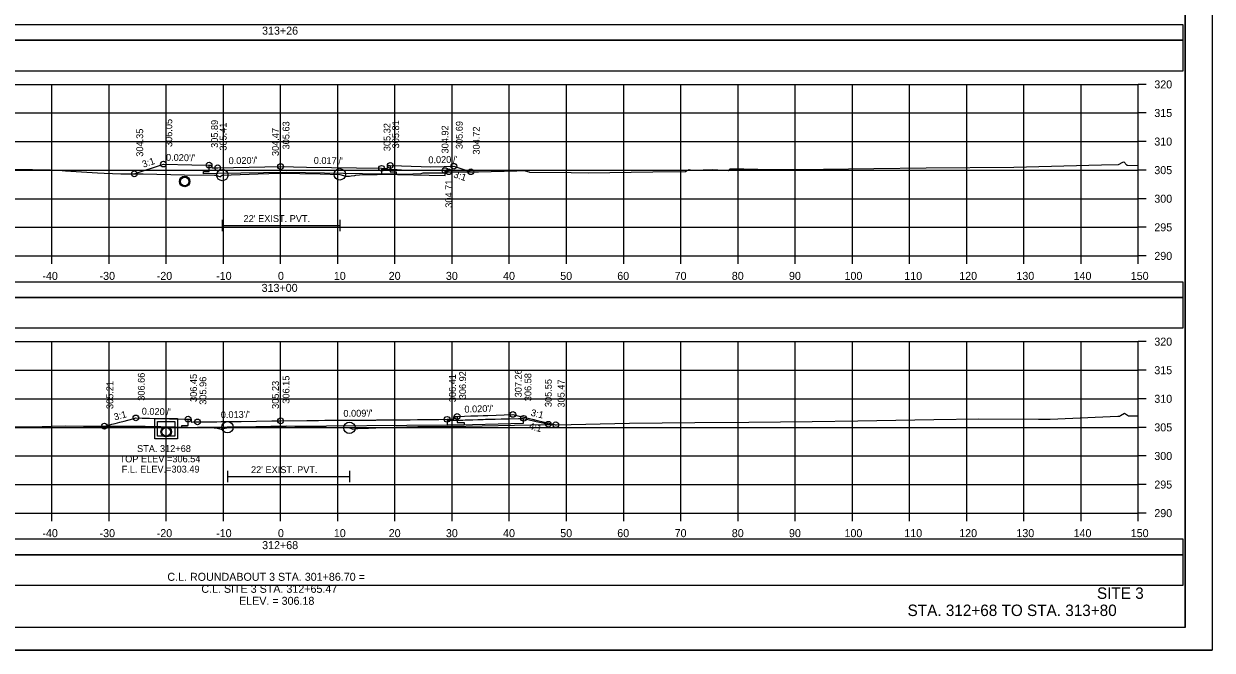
# Model space of a CAD drawing. Extents: x 1370538 to 1372872, y 376220 to 381127.
# Drawn here: x 1371330.4 to 1371538.2, y 378049.2 to 378158.8 of the extents above; entities that cross this region are included whole.
import ezdxf

# ---------------------------------------------------------------- set-up
doc = ezdxf.new("R2010")
doc.units = 0
for name, color, linetype in [('R_Border', 7, 'Continuous'), ('R_Border Notes', 7, 'Continuous'), ('R_Border PE', 7, 'Continuous'), ('R_Border Prem', 7, 'Continuous'), ('R_Dimension', 7, 'Continuous'), ('R_Fin Surface', 7, 'Continuous'), ('R_Grid', 7, 'Continuous'), ('R_Horz Alg Annot', 7, 'Continuous'), ('R_No Plot', 7, 'Continuous'), ('R_Proposed Road', 7, 'Continuous'), ('R_Water', 7, 'Continuous'), ('R_Water Annot', 7, 'Continuous'), ('R_Xsect Elev', 7, 'Continuous'), ('R_Xsect Slope', 7, 'Continuous')]:
    doc.layers.add(name, color=color, linetype=linetype)

msp = doc.modelspace()

# ---------------------------------------------------------------- linework, layer by layer
at = {"layer": 'R_Border'}
for p, q in [((1371365.1, 378124.52), (1371365.1, 378122.52)), ((1371385.64, 378124.52), (1371385.64, 378122.52)), ((1371365.1, 378123.52), (1371385.64, 378123.52)), ((1371366, 378080.59), (1371366, 378078.59)), ((1371366, 378079.59), (1371387.33, 378079.59)), ((1371387.33, 378080.59), (1371387.33, 378078.59))]:
    msp.add_line(p, q, dxfattribs=at)
for points in [[(1371376.35, 378132.79), (1371364.29, 378132.6), (1371361.79, 378132.55), (1371361.79, 378132.96), (1371362.79, 378132.98), (1371362.79, 378134.08)], [(1371394.47, 378134), (1371394.47, 378132.9), (1371395.48, 378132.89), (1371395.48, 378132.47), (1371392.96, 378132.51), (1371376.35, 378132.79)], [(1371376.27, 378088.34), (1371360.76, 378088.15), (1371358, 378088.11), (1371358, 378088.53), (1371359.11, 378088.54), (1371359.11, 378089.64)], [(1371406.18, 378090.11), (1371406.18, 378089.02), (1371407.37, 378089.02), (1371407.37, 378088.6), (1371404.4, 378088.6), (1371376.27, 378088.34)]]:
    msp.add_lwpolyline(points, dxfattribs=at)
at = {"layer": 'R_Border Notes'}
for q in [(1371533.47, 378258.65), (1371217.29, 378053.19)]:
    msp.add_line((1371533.47, 378053.19), q, dxfattribs=at)
at = {"layer": 'R_Border Prem'}
for p, q in [((1371525.29, 378118.19), (1371525.29, 378148.19)), ((1371526.69, 378148.19), (1371525.29, 378148.19)), ((1371526.69, 378143.19), (1371525.29, 378143.19)), ((1371526.69, 378138.19), (1371525.29, 378138.19)), ((1371526.69, 378133.19), (1371525.29, 378133.19)), ((1371526.69, 378128.19), (1371525.29, 378128.19)), ((1371526.69, 378123.19), (1371525.29, 378123.19)), ((1371225.29, 378118.19), (1371525.29, 378118.19)), ((1371335.29, 378116.79), (1371335.29, 378118.19)), ((1371345.29, 378116.79), (1371345.29, 378118.19)), ((1371355.29, 378116.79), (1371355.29, 378118.19)), ((1371365.29, 378116.79), (1371365.29, 378118.19)), ((1371375.29, 378116.79), (1371375.29, 378118.19)), ((1371385.29, 378116.79), (1371385.29, 378118.19)), ((1371395.29, 378116.79), (1371395.29, 378118.19)), ((1371405.29, 378116.79), (1371405.29, 378118.19)), ((1371415.29, 378116.79), (1371415.29, 378118.19)), ((1371425.29, 378116.79), (1371425.29, 378118.19)), ((1371435.29, 378116.79), (1371435.29, 378118.19)), ((1371445.29, 378116.79), (1371445.29, 378118.19)), ((1371455.29, 378116.79), (1371455.29, 378118.19)), ((1371465.29, 378116.79), (1371465.29, 378118.19)), ((1371475.29, 378116.79), (1371475.29, 378118.19)), ((1371485.29, 378116.79), (1371485.29, 378118.19)), ((1371495.29, 378116.79), (1371495.29, 378118.19)), ((1371505.29, 378116.79), (1371505.29, 378118.19)), ((1371515.29, 378116.79), (1371515.29, 378118.19)), ((1371525.29, 378116.79), (1371525.29, 378118.19)), ((1371526.69, 378118.19), (1371525.29, 378118.19)), ((1371525.29, 378073.19), (1371525.29, 378103.19)), ((1371526.69, 378103.19), (1371525.29, 378103.19)), ((1371526.69, 378098.19), (1371525.29, 378098.19)), ((1371526.69, 378093.19), (1371525.29, 378093.19)), ((1371526.69, 378088.19), (1371525.29, 378088.19)), ((1371526.69, 378083.19), (1371525.29, 378083.19)), ((1371526.69, 378078.19), (1371525.29, 378078.19)), ((1371225.29, 378073.19), (1371525.29, 378073.19)), ((1371335.29, 378071.79), (1371335.29, 378073.19)), ((1371345.29, 378071.79), (1371345.29, 378073.19)), ((1371355.29, 378071.79), (1371355.29, 378073.19)), ((1371365.29, 378071.79), (1371365.29, 378073.19)), ((1371375.29, 378071.79), (1371375.29, 378073.19)), ((1371385.29, 378071.79), (1371385.29, 378073.19)), ((1371395.29, 378071.79), (1371395.29, 378073.19)), ((1371405.29, 378071.79), (1371405.29, 378073.19)), ((1371415.29, 378071.79), (1371415.29, 378073.19)), ((1371425.29, 378071.79), (1371425.29, 378073.19)), ((1371435.29, 378071.79), (1371435.29, 378073.19)), ((1371445.29, 378071.79), (1371445.29, 378073.19)), ((1371455.29, 378071.79), (1371455.29, 378073.19)), ((1371465.29, 378071.79), (1371465.29, 378073.19)), ((1371475.29, 378071.79), (1371475.29, 378073.19)), ((1371485.29, 378071.79), (1371485.29, 378073.19)), ((1371495.29, 378071.79), (1371495.29, 378073.19)), ((1371505.29, 378071.79), (1371505.29, 378073.19)), ((1371515.29, 378071.79), (1371515.29, 378073.19)), ((1371525.29, 378071.79), (1371525.29, 378073.19)), ((1371526.69, 378073.19), (1371525.29, 378073.19))]:
    msp.add_line(p, q, dxfattribs=at)
at = {"layer": 'R_Dimension'}
for points in [[(1371325.83, 378133.33), (1371331.9, 378133.31), (1371335.03, 378133.22), (1371336.48, 378133.16), (1371337.67, 378133.06), (1371343.25, 378132.73), (1371344.42, 378132.66), (1371347.34, 378132.55), (1371349.07, 378132.54), (1371351.28, 378132.55), (1371358.46, 378132.39), (1371363.71, 378132.3), (1371363.92, 378132.29), (1371364.06, 378132.3), (1371364.33, 378132.19), (1371364.7, 378132.03), (1371364.92, 378132.21), (1371365.1, 378132.33), (1371371.38, 378132.54), (1371375.09, 378132.66), (1371382.19, 378132.52), (1371385.64, 378132.45), (1371386.31, 378132.25), (1371386.69, 378132.12), (1371387.36, 378132.16), (1371387.63, 378132.21), (1371388.28, 378132.27), (1371388.45, 378132.29), (1371389.09, 378132.36), (1371398.42, 378132.54), (1371399.84, 378132.6), (1371399.87, 378132.62), (1371400.2, 378132.69), (1371402.07, 378132.71), (1371403.89, 378132.73), (1371404.06, 378132.83), (1371404.46, 378132.9), (1371409.91, 378132.92), (1371416.61, 378133.06), (1371417.85, 378133.15), (1371418.69, 378132.9), (1371418.8, 378132.86), (1371426.08, 378132.79), (1371429.09, 378132.74), (1371440.4, 378132.9), (1371446.12, 378132.96), (1371446.26, 378133.04), (1371446.75, 378133.31), (1371447.22, 378133.18), (1371447.25, 378133.17), (1371447.52, 378133.19), (1371450.85, 378133.3), (1371453.54, 378133.12), (1371453.77, 378133.31), (1371453.9, 378133.39), (1371456.31, 378133.39), (1371458.71, 378133.35), (1371458.76, 378133.31), (1371458.99, 378133.31), (1371459.17, 378133.28), (1371465.78, 378133.33), (1371479.01, 378133.45), (1371488.17, 378133.59), (1371503.54, 378133.73), (1371518.88, 378134.1), (1371521.82, 378134.16), (1371522.6, 378134.61), (1371522.76, 378134.67), (1371523.3, 378134.06), (1371523.3, 378134.05), (1371523.46, 378134.05), (1371525.29, 378134.03)], [(1371325.69, 378088.3), (1371331.82, 378088.28), (1371335.32, 378088.43), (1371337.61, 378088.44), (1371340.8, 378088.4), (1371347.61, 378088.41), (1371350.69, 378088.4), (1371351.61, 378088.4), (1371354.36, 378088.34), (1371363.7, 378088.12), (1371363.96, 378088.12), (1371364.04, 378088.12), (1371364.21, 378088.05), (1371364.9, 378087.85), (1371365.82, 378088.13), (1371366, 378088.21), (1371368.29, 378088.27), (1371376.27, 378088.44), (1371379.26, 378088.36), (1371387.33, 378088.11), (1371387.63, 378087.98), (1371387.93, 378087.87), (1371388.38, 378087.96), (1371388.73, 378088), (1371388.81, 378088.02), (1371390.65, 378088.04), (1371393.25, 378088.18), (1371393.59, 378088.19), (1371399.29, 378088.34), (1371403.87, 378088.36), (1371404.87, 378088.36), (1371421.85, 378088.7), (1371422.71, 378088.71), (1371423.33, 378088.65), (1371423.57, 378088.64), (1371436.29, 378088.91), (1371447.72, 378089.06), (1371457.17, 378089.1), (1371468.26, 378089.24), (1371476.27, 378089.34), (1371489.54, 378089.55), (1371497.4, 378089.66), (1371507.84, 378089.61), (1371509.86, 378089.62), (1371521.72, 378090.14), (1371522.04, 378090.15), (1371522.06, 378090.15), (1371522.18, 378090.24), (1371522.87, 378090.7), (1371523.6, 378090.23), (1371523.6, 378090.23), (1371523.6, 378090.23), (1371525.29, 378090.23)]]:
    msp.add_lwpolyline(points, dxfattribs=at)
at = {"layer": 'R_Fin Surface'}
for points in [[(1371349.71, 378132.54), (1371354.79, 378134.24), (1371359.79, 378134.14), (1371362.79, 378134.08), (1371363.29, 378134.08), (1371363.29, 378133.58), (1371364.29, 378133.6), (1371375.29, 378133.82)], [(1371375.29, 378133.82), (1371379.85, 378133.73), (1371392.96, 378133.51), (1371393.96, 378133.5), (1371393.96, 378133.86), (1371393.96, 378134), (1371394.13, 378134), (1371394.47, 378134), (1371396.44, 378133.92), (1371401.56, 378133.76), (1371403.91, 378133.83), (1371405.59, 378133.87), (1371406.29, 378133.65), (1371408.57, 378132.91)], [(1371344.48, 378088.4), (1371344.96, 378088.52), (1371345.03, 378088.54), (1371345.59, 378088.68), (1371345.79, 378088.74), (1371346.37, 378088.89), (1371347.16, 378089.09), (1371347.91, 378089.29), (1371349.45, 378089.71), (1371349.6, 378089.75), (1371349.98, 378089.85), (1371351.07, 378089.83), (1371351.47, 378089.82), (1371352.36, 378089.8), (1371353.54, 378089.77), (1371353.65, 378089.77), (1371353.85, 378089.76), (1371354.63, 378089.74), (1371354.8, 378089.74), (1371355.76, 378089.72), (1371355.87, 378089.71), (1371357.24, 378089.68), (1371358.5, 378089.65), (1371359.11, 378089.64), (1371359.49, 378089.63), (1371359.66, 378089.63), (1371359.66, 378089.54), (1371359.66, 378089.13), (1371359.95, 378089.14), (1371360.41, 378089.14), (1371360.76, 378089.15), (1371361.07, 378089.15), (1371361.3, 378089.15), (1371363.02, 378089.17), (1371363.59, 378089.18), (1371364.14, 378089.19), (1371364.91, 378089.2), (1371367.6, 378089.23), (1371368.4, 378089.24), (1371373.78, 378089.32), (1371374, 378089.32), (1371374.24, 378089.33), (1371375.02, 378089.34), (1371375.07, 378089.34), (1371375.29, 378089.34)], [(1371375.29, 378089.34), (1371379.89, 378089.39), (1371381.91, 378089.42), (1371383, 378089.43), (1371384.69, 378089.45), (1371385.76, 378089.46), (1371386.31, 378089.47), (1371386.49, 378089.47), (1371387.02, 378089.48), (1371391.62, 378089.48), (1371391.66, 378089.48), (1371391.68, 378089.48), (1371391.92, 378089.48), (1371392.13, 378089.49), (1371392.3, 378089.49), (1371392.83, 378089.49), (1371395.01, 378089.52), (1371395.18, 378089.52), (1371395.67, 378089.52), (1371397.08, 378089.54), (1371397.94, 378089.54), (1371399.26, 378089.55), (1371401.67, 378089.58), (1371402.15, 378089.58), (1371402.95, 378089.59), (1371404.4, 378089.6), (1371405.31, 378089.6), (1371405.51, 378089.6), (1371405.58, 378089.6), (1371405.58, 378090.06), (1371405.58, 378090.1), (1371406.04, 378090.11), (1371406.18, 378090.11), (1371407.45, 378090.15), (1371408.54, 378090.19), (1371409.76, 378090.23), (1371409.79, 378090.23), (1371409.79, 378090.23), (1371410.73, 378090.27), (1371410.87, 378090.27), (1371411.55, 378090.29), (1371412.97, 378090.34), (1371414.38, 378090.39), (1371415.91, 378090.45), (1371417.04, 378090.17), (1371417.59, 378090.04), (1371419.55, 378089.57), (1371419.77, 378089.51), (1371419.98, 378089.46), (1371421.42, 378089.13), (1371421.92, 378089.01), (1371422.25, 378088.93), (1371423.41, 378088.66)]]:
    msp.add_lwpolyline(points, dxfattribs=at)
at = {"layer": 'R_Grid'}
for p, q in [((1371225.29, 378148.19), (1371525.29, 378148.19)), ((1371335.29, 378118.19), (1371335.29, 378148.19)), ((1371345.29, 378118.19), (1371345.29, 378148.19)), ((1371355.29, 378118.19), (1371355.29, 378148.19)), ((1371365.29, 378118.19), (1371365.29, 378148.19)), ((1371375.29, 378118.19), (1371375.29, 378148.19)), ((1371385.29, 378118.19), (1371385.29, 378148.19)), ((1371395.29, 378118.19), (1371395.29, 378148.19)), ((1371405.29, 378118.19), (1371405.29, 378148.19)), ((1371415.29, 378118.19), (1371415.29, 378148.19)), ((1371425.29, 378118.19), (1371425.29, 378148.19)), ((1371435.29, 378118.19), (1371435.29, 378148.19)), ((1371445.29, 378118.19), (1371445.29, 378148.19)), ((1371455.29, 378118.19), (1371455.29, 378148.19)), ((1371465.29, 378118.19), (1371465.29, 378148.19)), ((1371475.29, 378118.19), (1371475.29, 378148.19)), ((1371485.29, 378118.19), (1371485.29, 378148.19)), ((1371495.29, 378118.19), (1371495.29, 378148.19)), ((1371505.29, 378118.19), (1371505.29, 378148.19)), ((1371515.29, 378118.19), (1371515.29, 378148.19)), ((1371525.29, 378118.19), (1371525.29, 378148.19)), ((1371225.29, 378143.19), (1371525.29, 378143.19)), ((1371225.29, 378138.19), (1371525.29, 378138.19)), ((1371225.29, 378133.19), (1371525.29, 378133.19)), ((1371225.29, 378128.19), (1371525.29, 378128.19)), ((1371225.29, 378123.19), (1371525.29, 378123.19)), ((1371225.29, 378118.19), (1371525.29, 378118.19)), ((1371225.29, 378103.19), (1371525.29, 378103.19)), ((1371335.29, 378073.19), (1371335.29, 378103.19)), ((1371345.29, 378073.19), (1371345.29, 378103.19)), ((1371355.29, 378073.19), (1371355.29, 378103.19)), ((1371365.29, 378073.19), (1371365.29, 378103.19)), ((1371375.29, 378073.19), (1371375.29, 378103.19)), ((1371385.29, 378073.19), (1371385.29, 378103.19)), ((1371395.29, 378073.19), (1371395.29, 378103.19)), ((1371405.29, 378073.19), (1371405.29, 378103.19)), ((1371415.29, 378073.19), (1371415.29, 378103.19)), ((1371425.29, 378073.19), (1371425.29, 378103.19)), ((1371435.29, 378073.19), (1371435.29, 378103.19)), ((1371445.29, 378073.19), (1371445.29, 378103.19)), ((1371455.29, 378073.19), (1371455.29, 378103.19)), ((1371465.29, 378073.19), (1371465.29, 378103.19)), ((1371475.29, 378073.19), (1371475.29, 378103.19)), ((1371485.29, 378073.19), (1371485.29, 378103.19)), ((1371495.29, 378073.19), (1371495.29, 378103.19)), ((1371505.29, 378073.19), (1371505.29, 378103.19)), ((1371515.29, 378073.19), (1371515.29, 378103.19)), ((1371525.29, 378073.19), (1371525.29, 378103.19)), ((1371225.29, 378098.19), (1371525.29, 378098.19)), ((1371225.29, 378093.19), (1371525.29, 378093.19)), ((1371225.29, 378088.19), (1371525.29, 378088.19)), ((1371225.29, 378083.19), (1371525.29, 378083.19)), ((1371225.29, 378078.19), (1371525.29, 378078.19)), ((1371225.29, 378073.19), (1371525.29, 378073.19))]:
    msp.add_line(p, q, dxfattribs=at)
at = {"layer": 'R_Horz Alg Annot'}
for points in [[(1371218, 378155.92), (1371533.13, 378155.92), (1371533.13, 378158.62), (1371218, 378158.62)], [(1371218, 378150.59), (1371533.13, 378150.59), (1371533.13, 378155.92), (1371218, 378155.92)], [(1371218, 378110.91), (1371533.13, 378110.91), (1371533.13, 378113.62), (1371218, 378113.62)], [(1371218, 378105.59), (1371533.13, 378105.59), (1371533.13, 378110.91), (1371218, 378110.91)], [(1371218, 378065.9), (1371533.13, 378065.9), (1371533.13, 378068.61), (1371218, 378068.61)], [(1371218, 378060.58), (1371533.13, 378060.58), (1371533.13, 378065.9), (1371218, 378065.9)]]:
    msp.add_lwpolyline(points, close=True, dxfattribs=at)
for points in [[(1371392.96, 378133.34), (1371395.7, 378133.28), (1371396.44, 378133.26), (1371400.59, 378133.17), (1371404.05, 378133.11), (1371404.24, 378133.05), (1371404.71, 378132.9)], [(1371392.96, 378133.34), (1371392.96, 378132.51), (1371404.05, 378132.28), (1371404.05, 378133.11)], [(1371404.4, 378089.43), (1371405.31, 378089.45), (1371407.17, 378089.48), (1371407.59, 378089.5), (1371408.29, 378089.51), (1371408.54, 378089.52), (1371408.93, 378089.54), (1371409.79, 378089.56), (1371410.09, 378089.57), (1371410.29, 378089.58), (1371410.54, 378089.58), (1371410.73, 378089.59), (1371411.12, 378089.6), (1371411.55, 378089.61), (1371412.13, 378089.62), (1371412.81, 378089.64), (1371413.89, 378089.67), (1371414.38, 378089.68), (1371415, 378089.7), (1371415.18, 378089.7), (1371416.91, 378089.75), (1371417.04, 378089.75), (1371417.06, 378089.75), (1371417.41, 378089.76), (1371417.79, 378089.77), (1371419.51, 378089.35), (1371419.52, 378089.35), (1371419.55, 378089.35), (1371419.73, 378089.3), (1371419.98, 378089.24), (1371421.15, 378088.97), (1371421.56, 378088.87), (1371421.98, 378088.77), (1371422.11, 378088.74)], [(1371404.4, 378089.43), (1371404.4, 378088.6), (1371417.79, 378088.94), (1371417.79, 378089.77)]]:
    msp.add_lwpolyline(points, dxfattribs=at)
at = {"layer": 'R_No Plot'}
msp.add_line((1371204.89, 378049.21), (1371538.22, 378049.21), dxfattribs=at)
for points in [[(1371204.88, 378262.54), (1371538.22, 378262.54), (1371538.22, 378049.21), (1371204.88, 378049.21)], [(1371451.21, 378258.65), (1371451.21, 378248.77), (1371486.94, 378248.77), (1371486.94, 378245.85), (1371510.14, 378245.85), (1371510.14, 378221.52), (1371533.47, 378221.52), (1371533.47, 378053.19), (1371217.29, 378053.19), (1371217.29, 378258.65)]]:
    msp.add_lwpolyline(points, close=True, dxfattribs=at)
for centre, radius in [((1371349.71, 378132.54), 0.5), ((1371354.79, 378134.24), 0.5), ((1371362.79, 378134.08), 0.5), ((1371364.29, 378133.6), 0.5), ((1371365.1, 378132.33), 1), ((1371375.29, 378133.82), 0.5), ((1371375.29, 378133.82), 0.5), ((1371385.64, 378132.45), 1), ((1371392.96, 378133.51), 0.5), ((1371394.47, 378134), 0.5), ((1371404.05, 378133.11), 0.5), ((1371404.71, 378132.9), 0.5), ((1371405.59, 378133.87), 0.5), ((1371408.57, 378132.91), 0.5), ((1371358.52, 378131.21), 0.917), ((1371349.98, 378089.85), 0.5), ((1371359.11, 378089.64), 0.5), ((1371360.76, 378089.15), 0.5), ((1371366, 378088.21), 1), ((1371375.29, 378089.34), 0.5), ((1371375.29, 378089.34), 0.5), ((1371404.4, 378089.6), 0.5), ((1371406.18, 378090.11), 0.5), ((1371415.91, 378090.45), 0.5), ((1371417.79, 378089.77), 0.5), ((1371422.11, 378088.74), 0.5), ((1371423.41, 378088.66), 0.5), ((1371344.48, 378088.4), 0.5), ((1371355.29, 378087.43), 0.917), ((1371355.29, 378087.43), 0.917), ((1371387.33, 378088.11), 1)]:
    msp.add_circle(centre, radius, dxfattribs=at)
at = {"layer": 'R_Water'}
for points in [[(1371355.29, 378089.73), (1371357.29, 378089.73), (1371357.29, 378086.18), (1371355.29, 378086.18), (1371353.29, 378086.18), (1371353.29, 378089.73)], [(1371355.29, 378089.23), (1371356.79, 378089.23), (1371356.79, 378086.68), (1371355.29, 378086.68), (1371353.79, 378086.68), (1371353.79, 378089.23)]]:
    msp.add_lwpolyline(points, close=True, dxfattribs=at)
for centre in [(1371358.52, 378131.21), (1371355.29, 378087.43), (1371355.29, 378087.43)]:
    msp.add_circle(centre, 0.75, dxfattribs=at)
at = {"layer": 'R_Xsect Elev'}
for p, q in [((1371375.29, 378132.66), (1371375.29, 378142.66)), ((1371375.29, 378088.42), (1371375.29, 378098.42))]:
    msp.add_line(p, q, dxfattribs=at)

# ---------------------------------------------------------------- texts
at = {"layer": 'R_Border PE'}
for s, p in [('313+26', (1371372.05, 378156.89)), ('320', (1371528.09, 378147.49)), ('315', (1371528.09, 378142.49)), ('310', (1371528.09, 378137.49)), ('305', (1371528.09, 378132.49)), ('300', (1371528.09, 378127.49)), ('295', (1371528.09, 378122.49)), ('290', (1371528.09, 378117.49)), ('-40', (1371333.63, 378113.99)), ('-30', (1371343.63, 378113.99)), ('-20', (1371353.63, 378113.99)), ('-10', (1371364.02, 378113.99)), ('0', (1371374.83, 378113.99)), ('10', (1371384.6, 378113.99)), ('20', (1371394.2, 378113.99)), ('30', (1371404.2, 378113.99)), ('40', (1371414.2, 378113.99)), ('50', (1371424.2, 378113.99)), ('60', (1371434.17, 378113.99)), ('70', (1371444.2, 378113.99)), ('80', (1371454.2, 378113.99)), ('90', (1371464.2, 378113.99)), ('100', (1371473.91, 378113.99)), ('110', (1371484.37, 378113.99)), ('120', (1371493.97, 378113.99)), ('130', (1371503.97, 378113.99)), ('140', (1371513.97, 378113.99)), ('150', (1371523.97, 378113.99)), ('313+00', (1371371.97, 378111.89)), ('320', (1371528.09, 378102.49)), ('315', (1371528.09, 378097.49)), ('310', (1371528.09, 378092.49)), ('305', (1371528.09, 378087.49)), ('300', (1371528.09, 378082.49)), ('295', (1371528.09, 378077.49)), ('290', (1371528.09, 378072.49)), ('-40', (1371333.63, 378068.99)), ('-30', (1371343.63, 378068.99)), ('-20', (1371353.63, 378068.99)), ('-10', (1371364.02, 378068.99)), ('0', (1371374.83, 378068.99)), ('10', (1371384.6, 378068.99)), ('20', (1371394.2, 378068.99)), ('30', (1371404.2, 378068.99)), ('40', (1371414.2, 378068.99)), ('50', (1371424.2, 378068.99)), ('60', (1371434.17, 378068.99)), ('70', (1371444.2, 378068.99)), ('80', (1371454.2, 378068.99)), ('90', (1371464.2, 378068.99)), ('100', (1371473.91, 378068.99)), ('110', (1371484.37, 378068.99)), ('120', (1371493.97, 378068.99)), ('130', (1371503.97, 378068.99)), ('140', (1371513.97, 378068.99)), ('150', (1371523.97, 378068.99)), ('312+68', (1371372.06, 378066.89)), ('C.L. ROUNDABOUT 3 STA. 301+86.70 =', (1371355.49, 378061.35)), ('C.L. SITE 3 STA. 312+65.47', (1371361.43, 378059.25)), ('ELEV. = 306.18', (1371368.03, 378057.15))]:
    msp.add_text(s, height=1.4, dxfattribs=at).set_placement(p)
at = {"layer": 'R_Proposed Road'}
for s, p in [('SITE 3', (1371518.06, 378058.19)), ('STA. 312+68 TO STA. 313+80', (1371484.94, 378055.19))]:
    msp.add_text(s, height=2, dxfattribs=at).set_placement(p)
at = {"layer": 'R_Water'}
for p in [(1371368.82, 378124.12), (1371370.12, 378080.19)]:
    msp.add_text("22' EXIST. PVT.", height=1.2, dxfattribs=at).set_placement(p)
at = {"layer": 'R_Water Annot'}
for s, p in [('STA. 312+68', (1371350.19, 378083.88)), ('TOP ELEV.=306.54', (1371347.13, 378082.08)), ('F.L. ELEV.=303.49', (1371347.51, 378080.28))]:
    msp.add_text(s, height=1.2, dxfattribs=at).set_placement(p)
at = {"layer": 'R_Xsect Elev'}
for s, p in [('306.05', (1371356.34, 378137.24)), ('305.89', (1371364.34, 378137.08)), ('305.41', (1371365.84, 378136.6)), ('305.63', (1371376.84, 378136.82)), ('305.63', (1371376.84, 378136.82)), ('305.32', (1371394.51, 378136.51)), ('305.81', (1371396.02, 378137)), ('305.69', (1371407.14, 378136.87)), ('304.35', (1371351.26, 378135.54)), ('304.47', (1371374.99, 378135.66)), ('304.92', (1371404.65, 378136.11)), ('304.72', (1371410.12, 378135.91)), ('304.71', (1371405.31, 378126.61)), ('306.66', (1371351.53, 378092.85)), ('306.45', (1371360.66, 378092.64)), ('306.92', (1371407.73, 378093.11)), ('307.26', (1371417.46, 378093.45)), ('306.58', (1371419.15, 378092.77)), ('305.21', (1371346.03, 378091.4)), ('305.96', (1371362.31, 378092.15)), ('305.23', (1371374.99, 378091.42)), ('306.15', (1371376.84, 378092.34)), ('306.41', (1371405.95, 378092.6)), ('305.55', (1371422.71, 378091.74)), ('305.47', (1371424.96, 378091.66))]:
    msp.add_text(s, height=1.2, rotation=90, dxfattribs=at).set_placement(p)
at = {"layer": 'R_Xsect Slope'}
for s, rotation, p in [('3:1', 18.4349, (1371351.3, 378133.6)), ("0.020'/'", 358.8542, (1371355.24, 378134.83)), ("0.020'/'", 1.1458, (1371366.21, 378134.23)), ("0.017'/'", 359.0273, (1371381.08, 378134.29)), ("0.020'/'", 1.1458, (1371401.14, 378134.38)), ('3:1', 342.1517, (1371405.44, 378131.95)), ("0.020'/'", 358.6295, (1371351, 378090.43)), ("0.009'/'", 0.5171, (1371386.28, 378090.04)), ("0.020'/'", 1.9948, (1371407.46, 378090.76)), ('3:1', 346.6138, (1371418.97, 378090.24)), ('3:1', 14.7644, (1371346.3, 378089.4)), ("0.013'/'", 0.7584, (1371364.84, 378089.8)), ('4:1', 346.6088, (1371418.64, 378087.87))]:
    msp.add_text(s, height=1.2, rotation=rotation, dxfattribs=at).set_placement(p)

doc.saveas('drawing.dxf')
